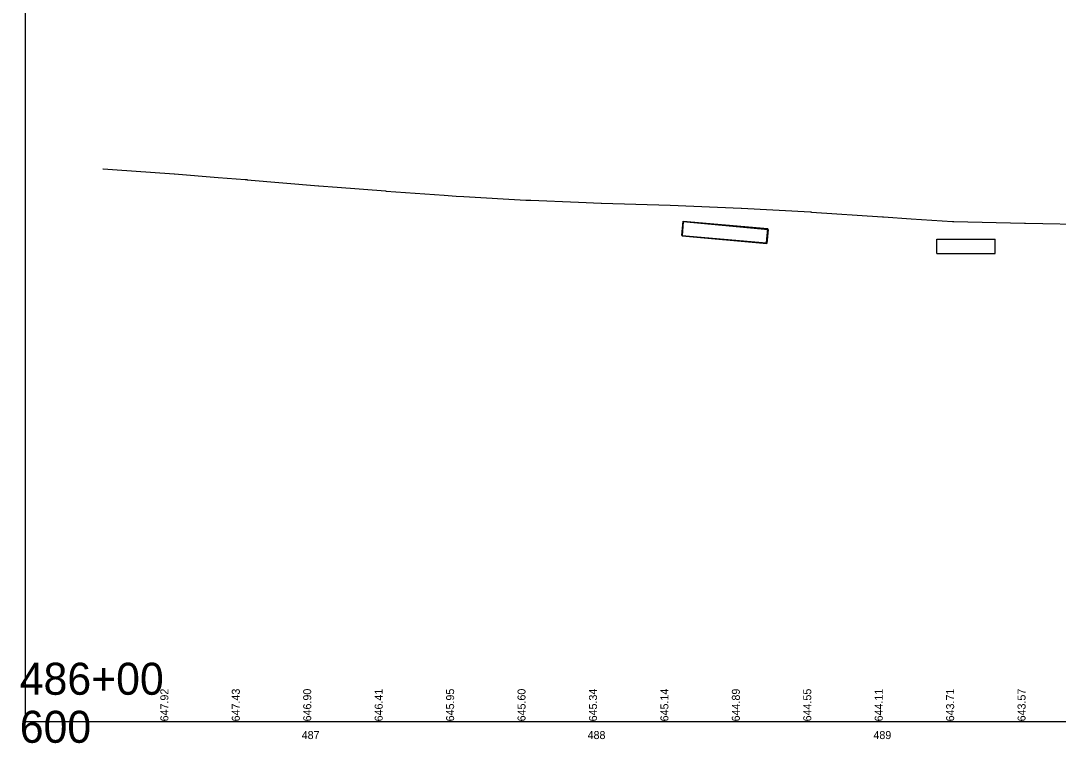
# Model space of a CAD drawing. Extents: x 2034057 to 2035954, y 247386 to 249135.
# Drawn here: x 2034990.1 to 2035353.2, y 248327.4 to 248580.1 of the extents above; entities that cross this region are included whole.
import ezdxf

# ---------------------------------------------------------------- set-up
doc = ezdxf.new("R2010")
doc.units = 0
for name, color, linetype in [('DR_X_Erosion_Control', 7, 'Continuous'), ('RD_X_Text', 7, 'Continuous'), ('SC_Scratch1', 7, 'Continuous'), ('SV_X_Toe_of_Slope', 7, 'Continuous'), ('SV_X_Top_of_Bank', 7, 'Continuous')]:
    doc.layers.add(name, color=color, linetype=linetype)

msp = doc.modelspace()

# ---------------------------------------------------------------- linework, layer by layer
at = {"layer": 'RD_X_Text'}
for p, q in [((2035222.03, 248509.89), (2035221.57, 248504.91)), ((2035222.03, 248509.89), (2035251.72, 248507.17)), ((2035221.57, 248504.91), (2035251.26, 248502.19)), ((2035251.72, 248507.17), (2035251.26, 248502.19)), ((2035310.75, 248498.71), (2035310.75, 248503.71)), ((2035310.75, 248503.71), (2035331.12, 248503.71)), ((2035331.12, 248498.71), (2035331.12, 248503.71)), ((2035310.75, 248498.71), (2035331.12, 248498.71))]:
    msp.add_line(p, q, dxfattribs=at)
at = {"layer": 'SC_Scratch1'}
msp.add_lwpolyline([(2035018.84, 248528.33), (2035018.97, 248528.32), (2035018.99, 248528.32), (2035022.24, 248528.09), (2035043.8, 248526.59), (2035043.97, 248526.58), (2035059.23, 248525.38), (2035065.56, 248524.87), (2035068.72, 248524.62), (2035068.72, 248524.62), (2035069.33, 248524.57), (2035069.41, 248524.56), (2035094.32, 248522.46), (2035094.42, 248522.46), (2035100.84, 248521.95), (2035117.79, 248520.61), (2035118.07, 248520.58), (2035138.35, 248519.12), (2035142.58, 248518.82), (2035145.23, 248518.67), (2035166.88, 248517.45), (2035167.38, 248517.42), (2035168.23, 248517.38), (2035168.7, 248517.37), (2035185.29, 248516.71), (2035193.22, 248516.39), (2035193.44, 248516.37), (2035217.48, 248515.59), (2035217.48, 248515.59), (2035242.23, 248514.59), (2035242.37, 248514.59), (2035242.37, 248514.59), (2035266.58, 248513.27), (2035266.61, 248513.27), (2035266.91, 248513.25), (2035291.7, 248511.53), (2035291.9, 248511.51), (2035292.05, 248511.51), (2035301.81, 248510.88), (2035316.2, 248509.95), (2035316.5, 248509.93), (2035316.73, 248509.93), (2035316.74, 248509.93), (2035341.44, 248509.38), (2035341.74, 248509.37), (2035365.98, 248508.92)], dxfattribs=at)
at = {"layer": 'SV_X_Toe_of_Slope'}
for q in [(2034991.81, 249135.07), (2035953.99, 248335.07)]:
    msp.add_line((2034991.81, 248335.07), q, dxfattribs=at)
at = {"layer": 'SV_X_Top_of_Bank'}
for p, q in [((2035221.51, 248505.07), (2035221.95, 248510.05)), ((2035221.95, 248510.05), (2035251.56, 248507.45)), ((2035221.51, 248505.07), (2035251.12, 248502.47)), ((2035251.12, 248502.47), (2035251.56, 248507.45))]:
    msp.add_line(p, q, dxfattribs=at)

# ---------------------------------------------------------------- texts
at = {"layer": 'DR_X_Erosion_Control'}
for s, p in [('647.92', (2035041.81, 248335.07)), ('647.43', (2035066.81, 248335.07)), ('646.90', (2035091.81, 248335.07)), ('646.41', (2035116.81, 248335.07)), ('645.95', (2035141.81, 248335.07)), ('645.60', (2035166.81, 248335.07)), ('645.34', (2035191.81, 248335.07)), ('645.14', (2035216.81, 248335.07)), ('644.89', (2035241.81, 248335.07)), ('644.55', (2035266.81, 248335.07)), ('644.11', (2035291.81, 248335.07)), ('643.71', (2035316.81, 248335.07)), ('643.57', (2035341.81, 248335.07))]:
    msp.add_text(s, height=2.8, rotation=90, dxfattribs=at).set_placement(p)
for s, p in [('487', (2035088.47, 248328.89)), ('488', (2035188.53, 248328.89)), ('489', (2035288.56, 248328.89))]:
    msp.add_text(s, height=2.8, dxfattribs=at).set_placement(p)
at = {"layer": 'SV_X_Toe_of_Slope'}
for s, p in [('486+00', (2034989.8, 248344.39)), ('600', (2034989.8, 248327.59))]:
    msp.add_text(s, height=11.2, dxfattribs=at).set_placement(p)

doc.saveas('drawing.dxf')
